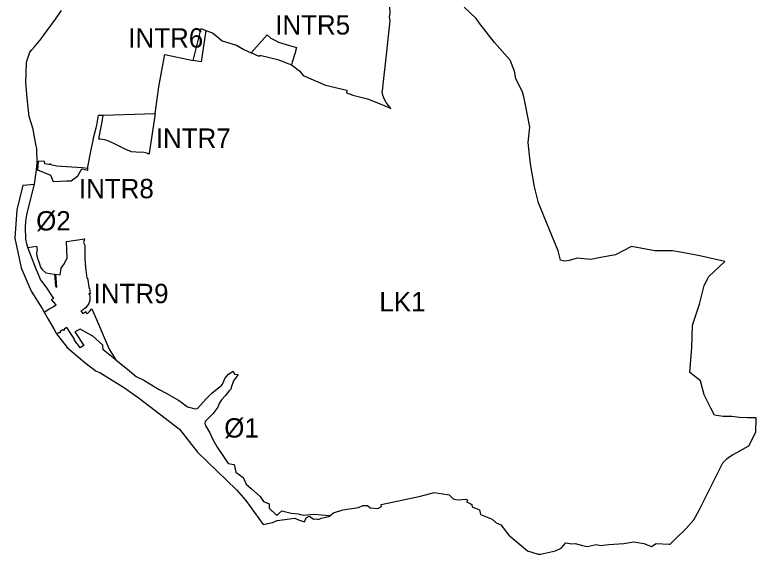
# Model space of a CAD drawing. Extents: x -754919 to -751903, y -1143879 to -1139906.
# Drawn here: x -754919 to -752241, y -1143879 to -1141930 of the extents above; entities that cross this region are included whole.
import ezdxf

# ---------------------------------------------------------------- set-up
doc = ezdxf.new("R2010")
doc.units = 0
for name, color, linetype in [('Vrstva 13', 7, 'Continuous'), ('Vrstva 2', 7, 'Continuous'), ('Vrstva 4', 7, 'Continuous'), ('Vrstva 5', 7, 'Continuous'), ('Vrstva 6', 7, 'Continuous')]:
    doc.layers.add(name, color=color, linetype=linetype)

msp = doc.modelspace()

# ---------------------------------------------------------------- linework, layer by layer
at = {"layer": 'Vrstva 13'}
for p, q in [((-753252.88, -1141942.87), (-753296.14, -1141902.04)), ((-754771.49, -1141945.5), (-754750.23, -1141914.45)), ((-754814.79, -1142003.9), (-754771.49, -1141945.5)), ((-753237.5, -1141963.98), (-753252.88, -1141942.87)), ((-753186.72, -1142029.75), (-753237.5, -1141963.98)), ((-754823.8, -1142016.05), (-754814.79, -1142003.9)), ((-754847.29, -1142045.42), (-754823.8, -1142016.05)), ((-753129.99, -1142093.96), (-753186.72, -1142029.75)), ((-754863.77, -1142065.09), (-754856.58, -1142056.5)), ((-754856.58, -1142056.5), (-754847.29, -1142045.42)), ((-754876.24, -1142100.3), (-754863.77, -1142065.09)), ((-754877.56, -1142142.55), (-754876.24, -1142100.3)), ((-753114.2, -1142133.5), (-753129.99, -1142093.96)), ((-754878.5, -1142175.65), (-754877.56, -1142142.55)), ((-753109, -1142160.85), (-753114.2, -1142133.5)), ((-753085.62, -1142208.37), (-753109, -1142160.85)), ((-754872.82, -1142242.62), (-754878.5, -1142175.65)), ((-753080.55, -1142226.05), (-753085.62, -1142208.37)), ((-754866.56, -1142297.23), (-754872.82, -1142242.62)), ((-753074.73, -1142255.5), (-753080.55, -1142226.05)), ((-753059.14, -1142335.81), (-753074.73, -1142255.5)), ((-754852.32, -1142342.51), (-754866.56, -1142297.23)), ((-754849.34, -1142358.49), (-754852.32, -1142342.51)), ((-753065.03, -1142390.58), (-753059.14, -1142335.81)), ((-754841.03, -1142403.13), (-754849.34, -1142358.49)), ((-754839.24, -1142412.73), (-754841.03, -1142403.13)), ((-753058.97, -1142447.9), (-753065.03, -1142390.58)), ((-754837.46, -1142465.1), (-754839.24, -1142412.73)), ((-753055, -1142474.95), (-753058.97, -1142447.9)), ((-754846.91, -1142541.79), (-754839.83, -1142490.01)), ((-754839.83, -1142490.01), (-754837.46, -1142465.1)), ((-753041.91, -1142551.42), (-753055, -1142474.95)), ((-754889.25, -1142544.97), (-754911.31, -1142634.54)), ((-754889.25, -1142544.97), (-754846.91, -1142541.79)), ((-753026.97, -1142609.18), (-753041.91, -1142551.42)), ((-753009.26, -1142653.81), (-753026.97, -1142609.18)), ((-754911.31, -1142634.54), (-754918.51, -1142736.76)), ((-752987.85, -1142706.31), (-753009.26, -1142653.81)), ((-752955.79, -1142783.11), (-752987.85, -1142706.31)), ((-754918.51, -1142736.76), (-754895.92, -1142843.98)), ((-752947.6, -1142816.21), (-752955.79, -1142783.11)), ((-752691.03, -1142767.17), (-752749.57, -1142797.49)), ((-752606.85, -1142782.64), (-752691.03, -1142767.17)), ((-752543.13, -1142783.25), (-752606.85, -1142782.64)), ((-752515.25, -1142787.94), (-752543.13, -1142783.25)), ((-752887.09, -1142809.28), (-752916.25, -1142817.74)), ((-752837.67, -1142813.59), (-752887.09, -1142809.28)), ((-752809.03, -1142807.65), (-752837.67, -1142813.59)), ((-752749.57, -1142797.49), (-752809.03, -1142807.65)), ((-752508.96, -1142789.1), (-752515.25, -1142787.94)), ((-752445.12, -1142800.96), (-752508.96, -1142789.1)), ((-752354.73, -1142821.69), (-752445.12, -1142800.96)), ((-752933.63, -1142820.15), (-752947.6, -1142816.21)), ((-752916.25, -1142817.74), (-752933.63, -1142820.15)), ((-752411.69, -1142876.01), (-752354.73, -1142821.69)), ((-754895.92, -1142843.98), (-754859.08, -1142927.93)), ((-752428.7, -1142907.43), (-752415.13, -1142882.37)), ((-752415.13, -1142882.37), (-752411.69, -1142876.01)), ((-752445.42, -1142975.43), (-752428.7, -1142907.43)), ((-754859.08, -1142927.93), (-754819.48, -1142991.3)), ((-754819.48, -1142991.3), (-754812.04, -1143004.22)), ((-752471.57, -1143051.57), (-752445.42, -1142975.43)), ((-754812.04, -1143004.22), (-754797.52, -1143029.44)), ((-754797.52, -1143029.44), (-754776.79, -1143066.66)), ((-752472.98, -1143131.45), (-752471.57, -1143051.57)), ((-754776.79, -1143066.66), (-754769.05, -1143080.55)), ((-754769.05, -1143080.55), (-754767.56, -1143082.49)), ((-754767.56, -1143082.49), (-754729.61, -1143131.94)), ((-754729.61, -1143131.94), (-754666.11, -1143186.71)), ((-752481.09, -1143222.1), (-752472.98, -1143131.45)), ((-754666.11, -1143186.71), (-754624.96, -1143217.22)), ((-754624.96, -1143217.22), (-754610.91, -1143222.08)), ((-754610.91, -1143222.08), (-754522.74, -1143278.2)), ((-752442.69, -1143251.97), (-752481.09, -1143222.1)), ((-752429.44, -1143303.43), (-752442.69, -1143251.97)), ((-754522.74, -1143278.2), (-754468.34, -1143316.29)), ((-754468.34, -1143316.29), (-754323.61, -1143426.58)), ((-752404.52, -1143351.09), (-752429.44, -1143303.43)), ((-752391.13, -1143376.11), (-752404.52, -1143351.09)), ((-752360.22, -1143381.3), (-752391.13, -1143376.11)), ((-752329.6, -1143381.86), (-752360.22, -1143381.3)), ((-752301.89, -1143385.36), (-752329.6, -1143381.86)), ((-752272.8, -1143386.74), (-752301.89, -1143385.36)), ((-752241.13, -1143386.43), (-752272.8, -1143386.74)), ((-752242.01, -1143437.97), (-752241.13, -1143386.43)), ((-754323.61, -1143426.58), (-754258.99, -1143510.59)), ((-752267.65, -1143487.5), (-752242.01, -1143437.97)), ((-752321.4, -1143517.58), (-752267.65, -1143487.5)), ((-754258.99, -1143510.59), (-754117.39, -1143646.84)), ((-752362.11, -1143548.38), (-752346.34, -1143532.86)), ((-752346.34, -1143532.86), (-752335.89, -1143525.42)), ((-752335.89, -1143525.42), (-752326.39, -1143520.37)), ((-752326.39, -1143520.37), (-752321.4, -1143517.58)), ((-752446.68, -1143719.8), (-752362.11, -1143548.38)), ((-754117.39, -1143646.84), (-754084.32, -1143684.77)), ((-753595.48, -1143699.37), (-753453.3, -1143668.83)), ((-753453.3, -1143668.83), (-753403.89, -1143655.66)), ((-753403.89, -1143655.66), (-753356.67, -1143662.8)), ((-753356.67, -1143662.8), (-753349.67, -1143664.13)), ((-753349.67, -1143664.13), (-753335.17, -1143679.35)), ((-754084.32, -1143684.77), (-754021.62, -1143772.32)), ((-753335.17, -1143679.35), (-753325.34, -1143681.51)), ((-753325.34, -1143681.51), (-753317.03, -1143683.11)), ((-753317.03, -1143683.11), (-753287.06, -1143679.61)), ((-753287.06, -1143679.61), (-753281.9, -1143685.09)), ((-753281.9, -1143685.09), (-753286.79, -1143689.39)), ((-753286.79, -1143689.39), (-753274.27, -1143696.02)), ((-753274.27, -1143696.02), (-753268, -1143699.96)), ((-753767.12, -1143729.97), (-753733.54, -1143718.3)), ((-753733.54, -1143718.3), (-753677.81, -1143710.2)), ((-753677.81, -1143710.2), (-753661.22, -1143703.31)), ((-753661.22, -1143703.31), (-753644.61, -1143703.21)), ((-753644.61, -1143703.21), (-753634.83, -1143711.68)), ((-753634.83, -1143711.68), (-753606.97, -1143713.79)), ((-753606.97, -1143713.79), (-753593.68, -1143706.83)), ((-753593.68, -1143706.83), (-753595.48, -1143699.37)), ((-753268, -1143699.96), (-753267.02, -1143708.27)), ((-753267.02, -1143708.27), (-753246.09, -1143716.75)), ((-753246.09, -1143716.75), (-753240, -1143719.24)), ((-753240, -1143719.24), (-753236.67, -1143735.69)), ((-752466.53, -1143754.93), (-752446.68, -1143719.8)), ((-753971.06, -1143757.02), (-753907.86, -1143748.49)), ((-753907.86, -1143748.49), (-753894.5, -1143755.33)), ((-753872.17, -1143761.94), (-753866.37, -1143747.15)), ((-753866.37, -1143747.15), (-753855.78, -1143742.15)), ((-753855.78, -1143742.15), (-753838.2, -1143752.89)), ((-753822.06, -1143753.5), (-753812.42, -1143748.65)), ((-753812.42, -1143748.65), (-753784.88, -1143742.72)), ((-753784.88, -1143742.72), (-753779.95, -1143739.18)), ((-753779.95, -1143739.18), (-753767.12, -1143729.97)), ((-753236.67, -1143735.69), (-753194.24, -1143752.34)), ((-754021.62, -1143772.32), (-753987.56, -1143763.98)), ((-753987.56, -1143763.98), (-753971.06, -1143757.02)), ((-753894.5, -1143755.33), (-753872.17, -1143761.94)), ((-753838.2, -1143752.89), (-753830.4, -1143750.91)), ((-753830.4, -1143750.91), (-753822.06, -1143753.5)), ((-753194.24, -1143752.34), (-753180.6, -1143765.25)), ((-753180.6, -1143765.25), (-753163.77, -1143772.69)), ((-753163.77, -1143772.69), (-753134.36, -1143810.15)), ((-752494.45, -1143786.04), (-752466.53, -1143754.93)), ((-752537.4, -1143828.38), (-752494.45, -1143786.04)), ((-753134.36, -1143810.15), (-753111.07, -1143829.89)), ((-753111.07, -1143829.89), (-753067.05, -1143867.2)), ((-752551.88, -1143842.65), (-752537.4, -1143828.38)), ((-752945.84, -1143857.41), (-752928.91, -1143838.57)), ((-752928.91, -1143838.57), (-752906.64, -1143841.6)), ((-752906.64, -1143841.6), (-752894.34, -1143839.97)), ((-752894.34, -1143839.97), (-752868.76, -1143848.2)), ((-752868.76, -1143848.2), (-752851.48, -1143850.87)), ((-752851.48, -1143850.87), (-752818.7, -1143843.6)), ((-752818.7, -1143843.6), (-752803.65, -1143847.07)), ((-752803.65, -1143847.07), (-752772.74, -1143844.35)), ((-752772.74, -1143844.35), (-752718.92, -1143840.11)), ((-752718.92, -1143840.11), (-752683.37, -1143834.87)), ((-752683.37, -1143834.87), (-752647.14, -1143840.74)), ((-752647.14, -1143840.74), (-752618.66, -1143851.71)), ((-752618.66, -1143851.71), (-752602.64, -1143840.13)), ((-752602.64, -1143840.13), (-752555.32, -1143842.5)), ((-752555.32, -1143842.5), (-752551.88, -1143842.65)), ((-753067.05, -1143867.2), (-753028.58, -1143878.83)), ((-753028.58, -1143878.83), (-753019.11, -1143879)), ((-753019.11, -1143879), (-753008.63, -1143876.5)), ((-753008.63, -1143876.5), (-752966.32, -1143866.4)), ((-752966.32, -1143866.4), (-752945.84, -1143857.41))]:
    msp.add_line(p, q, dxfattribs=at)
at = {"layer": 'Vrstva 2'}
for points in [[(-754274.43, -1142095.04), (-754245.61, -1141979.17), (-754228.94, -1141985.79), (-754245.81, -1142100.09)], [(-753919.26, -1142110.81), (-753931.04, -1142107.23), (-753963.8, -1142093.37), (-754033.42, -1142077.04), (-754036.55, -1142080.48), (-754064.97, -1142067.16), (-754007.56, -1142002.46), (-753993.57, -1142014.39), (-753981.74, -1142020.25), (-753966.13, -1142028.33), (-753927, -1142040.06), (-753901.31, -1142048.04), (-753907.75, -1142070.55), (-753916.33, -1142100.56)]]:
    msp.add_lwpolyline(points, close=True, dxfattribs=at)
for points in [[(-754411.44, -1142286.1), (-754424.72, -1142373.77), (-754433.24, -1142430.09), (-754433.69, -1142433.05), (-754441.27, -1142430.14), (-754452.43, -1142426.71), (-754480.75, -1142426.55), (-754497.24, -1142424.48), (-754518.08, -1142416.43), (-754556.41, -1142396.99), (-754576.06, -1142387.97), (-754593.84, -1142381.54), (-754610.54, -1142379.51), (-754614.76, -1142379.55), (-754614.04, -1142375.69), (-754613.37, -1142371.87), (-754608.78, -1142347.16), (-754603.02, -1142315.91), (-754599.03, -1142292.77), (-754411.44, -1142286.1)], [(-754833.81, -1142458.87), (-754836.92, -1142489.97), (-754789.36, -1142509.09), (-754780.07, -1142532.07), (-754731.9, -1142529.27), (-754724.42, -1142529.44), (-754715.42, -1142529.65), (-754700.73, -1142518.42), (-754691.24, -1142511.16), (-754677.11, -1142486.64), (-754655.15, -1142491.6), (-754654.85, -1142484.65), (-754675.03, -1142483.03), (-754768.35, -1142476.16), (-754787.95, -1142472.29), (-754787.95, -1142469.97), (-754792.58, -1142469.93), (-754792.58, -1142470.68), (-754796.22, -1142470.66), (-754810.26, -1142467.89), (-754810.97, -1142459.91), (-754833.81, -1142458.87)], [(-754871.53, -1142770.81), (-754840.15, -1142765.95), (-754838.27, -1142779.55), (-754840.56, -1142789.58), (-754839.27, -1142800.96), (-754837.12, -1142809.24), (-754829.13, -1142829.81), (-754825.34, -1142842.11), (-754820.17, -1142850), (-754806.59, -1142862.61), (-754774.96, -1142866.77), (-754771.24, -1142910.67), (-754766.29, -1142913.75), (-754769.97, -1142866.72), (-754754.44, -1142868.81), (-754750.83, -1142845), (-754739.16, -1142828.57), (-754729.64, -1142808.2), (-754731.52, -1142749.12), (-754667.21, -1142739.18), (-754670.01, -1142753.15), (-754665.31, -1142762.16), (-754665.84, -1142811.77), (-754663.52, -1142842.49), (-754658.9, -1142881.4), (-754656.23, -1142880.91), (-754649.59, -1142919.47), (-754648.54, -1142918.46), (-754646.03, -1142938.23), (-754650.67, -1142937.37), (-754647.68, -1142944.96), (-754647.83, -1142961.91), (-754651.71, -1142972.42), (-754656.38, -1142980.25), (-754663.14, -1142988.35), (-754672.22, -1142995.69), (-754679.65, -1143000.84), (-754677.89, -1143003.21), (-754673.28, -1143009.68), (-754662.53, -1143002.36), (-754660.88, -1143006.74), (-754657.25, -1143009.96), (-754649.16, -1143002.36), (-754640.38, -1142992.4), (-754619.45, -1143038.84), (-754596.08, -1143096.05), (-754578.36, -1143138.42), (-754553.96, -1143176.14), (-754562.91, -1143169.29), (-754599.95, -1143140.94), (-754601.01, -1143123.03), (-754636.5, -1143091.41), (-754639.45, -1143089.78), (-754682.27, -1143066.18), (-754701.36, -1143075.54), (-754669.6, -1143124.5), (-754682.96, -1143132.98), (-754690.5, -1143121.49), (-754694.58, -1143117.13), (-754703.82, -1143102.79), (-754702.9, -1143102.21), (-754730.37, -1143059.2), (-754735.06, -1143062.24), (-754740.43, -1143065.72), (-754739.83, -1143068.04), (-754740.56, -1143070.22), (-754742.91, -1143069.78), (-754744.6, -1143068.25), (-754754.85, -1143074.81), (-754754.21, -1143076.98), (-754754.83, -1143079.28), (-754757.34, -1143078.83), (-754758.95, -1143077.33), (-754767.56, -1143082.49)], [(-754812.04, -1143004.22), (-754791.58, -1142991.51), (-754782.3, -1142985.75), (-754778.26, -1142984.21), (-754769.5, -1142977.66), (-754786.2, -1142958.66), (-754777.83, -1142953.57), (-754780.21, -1142951.88), (-754804.82, -1142913.21), (-754825.62, -1142886.02), (-754836.49, -1142860.22), (-754841.23, -1142848.97), (-754871.53, -1142770.81)]]:
    msp.add_lwpolyline(points, dxfattribs=at)
at = {"layer": 'Vrstva 4'}
msp.add_line((-754839.83, -1142490.01), (-754836.92, -1142489.97), dxfattribs=at)
for points in [[(-753565.73, -1141937.09), (-753562.91, -1141923.3), (-753567.33, -1141829.76), (-753569.37, -1141819.95), (-753608.1, -1141734.59), (-753613.17, -1141713.65), (-753730.93, -1141692.68), (-753715.11, -1141602.56)], [(-753919.26, -1142110.81), (-753905.85, -1142120.65), (-753893.64, -1142129.61), (-753890.2, -1142132.13), (-753876.88, -1142149.45), (-753796.43, -1142183.69), (-753719.95, -1142201.56), (-753721.15, -1142211.95), (-753697.73, -1142219.81), (-753644.98, -1142232.92), (-753593.08, -1142253.37), (-753560.03, -1142267.78), (-753577.59, -1142246.26), (-753583.11, -1142235.35), (-753589.23, -1142219.53), (-753591.35, -1142207.67), (-753589.4, -1142195.65), (-753587.82, -1142181.81), (-753575.68, -1142073.72), (-753562.87, -1141950.74), (-753565.73, -1141937.09)], [(-754228.94, -1141985.79), (-754205.03, -1141995.29), (-754185.81, -1142010.65), (-754169.21, -1142023.39), (-754117.73, -1142038.82), (-754091.15, -1142054.9), (-754064.97, -1142067.16)], [(-754411.44, -1142286.1), (-754398.75, -1142189.53), (-754379.13, -1142084.65), (-754376.62, -1142073.27), (-754274.43, -1142095.04)], [(-754654.85, -1142484.65), (-754654.62, -1142479.53), (-754642.66, -1142417.9), (-754634.85, -1142377.71), (-754633.95, -1142374.35), (-754624.25, -1142338.16), (-754621.82, -1142328.35), (-754615.83, -1142292.4), (-754599.03, -1142292.77)]]:
    msp.add_lwpolyline(points, dxfattribs=at)
at = {"layer": 'Vrstva 5'}
for points in [[(-754871.53, -1142770.81), (-754875.27, -1142757.09), (-754878.53, -1142740.59), (-754880.17, -1142697.4), (-754878.82, -1142676.86), (-754875.18, -1142653.06), (-754869.69, -1142626.92), (-754846.91, -1142541.79)], [(-754553.96, -1143176.14), (-754504.96, -1143216.71), (-754480.31, -1143236.3), (-754452.24, -1143250.5), (-754437.47, -1143259.92), (-754397.39, -1143283.27), (-754372.25, -1143296.77), (-754327.36, -1143322.9), (-754313.61, -1143331.6), (-754295.25, -1143346.76), (-754266.81, -1143353.63), (-754258.45, -1143352.24), (-754227.25, -1143317.44), (-754207.05, -1143296.76), (-754187.22, -1143281.97), (-754173.38, -1143270.29), (-754169.07, -1143264.14), (-754163.56, -1143253.45), (-754160.17, -1143244.56), (-754160.17, -1143244.56), (-754146.44, -1143228.16), (-754130.18, -1143217.09), (-754125.27, -1143228.81), (-754111.5, -1143229.36), (-754121.39, -1143242.42), (-754129.15, -1143252.71), (-754137.61, -1143276.44), (-754138.81, -1143282.53), (-754145.19, -1143289.63), (-754158.88, -1143306.26), (-754171.86, -1143321.74), (-754180.75, -1143334.29), (-754185.89, -1143347.37), (-754203.26, -1143371.48), (-754221.91, -1143390.1), (-754231.59, -1143399.5), (-754232.32, -1143406.15), (-754228.99, -1143416.56), (-754214.72, -1143440), (-754204.59, -1143462.64), (-754187.63, -1143492.23), (-754166.92, -1143522.94), (-754148.43, -1143551.11), (-754126.72, -1143555.07), (-754120, -1143582.73), (-754094.35, -1143601.41), (-754083.25, -1143626.3), (-754064.05, -1143643.03), (-754032.29, -1143669.97), (-754020.62, -1143688.53), (-754000.28, -1143697.47), (-753999.99, -1143713.25), (-753973.67, -1143738.29), (-753966.09, -1143733.07), (-753953.77, -1143721.75), (-753920.82, -1143731.35), (-753895.26, -1143733.06), (-753875.4, -1143738.31), (-753835.66, -1143734.52), (-753811.52, -1143737.09), (-753784.88, -1143739.14), (-753779.95, -1143739.18)]]:
    msp.add_lwpolyline(points, dxfattribs=at)

# ---------------------------------------------------------------- texts
at = {"layer": 'Vrstva 4'}
for s, p in [('Ø2', (-754841.48, -1142709.08)), ('LK1', (-753602.04, -1143001.84)), ('Ø1', (-754162.29, -1143457.62))]:
    msp.add_text(s, height=70, dxfattribs=at).set_placement(p)
at = {"layer": 'Vrstva 6'}
for s, p in [('INTR5', (-753978.13, -1142001.07)), ('INTR6', (-754508.54, -1142048.26)), ('INTR7', (-754409.32, -1142410.44)), ('INTR8', (-754687.03, -1142592.64)), ('INTR9', (-754633.83, -1142971.9))]:
    msp.add_text(s, height=70, dxfattribs=at).set_placement(p)

doc.saveas('drawing.dxf')
